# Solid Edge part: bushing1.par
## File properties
Title: Bushing
Author: Deepak Maini
Template: normal.par
Last saved by: CADCIM
Revision: 4
Application: Solid Edge
Density: 0.28179277014 lbm/in^3
Accuracy: 0.01
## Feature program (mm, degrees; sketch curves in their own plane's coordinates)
sketch for "unnamed RevolvedProtrusion 1" plane through (0, 0, -8.3976) normal (0, 0, 1) x-axis (1, 0, 0)
  line (-23.1281, 31.75) -> (-23.1281, 34.9556)
  line (-23.1281, 34.9556) -> (-38.3879, 34.9556)
  line (-38.3879, 34.9556) -> (-38.3879, 31.75)
  line (-38.3879, 31.75) -> (-23.1281, 31.75)
revolve "unnamed RevolvedProtrusion 1" add full turn 360 deg about sketch line (-48.5775, 25.4) -> (54.7954, 25.4)
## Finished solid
Body 1: solid body, 4 faces, 4 edges, 0 vertices.
  Faces by surface: cylinder 2, plane 2
  Edges by curve: circle 4
Bounding box of the edges (mm): 15.260 x 19.111 x 19.111, from (-38.3879, 15.8444, -17.9532) to (-23.1281, 34.9556, 1.1579).
Cylindrical faces by radius (mm): R6.35 x1, R9.5556 x1
Planar faces by outward normal: +x 1, -x 1
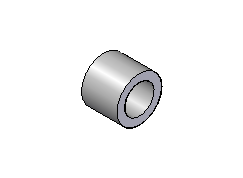
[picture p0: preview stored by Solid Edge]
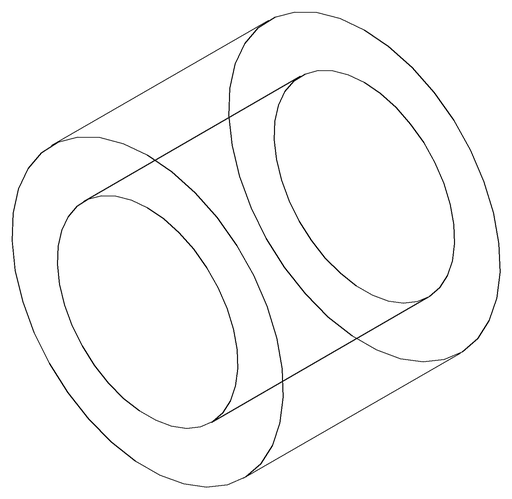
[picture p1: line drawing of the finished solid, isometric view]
